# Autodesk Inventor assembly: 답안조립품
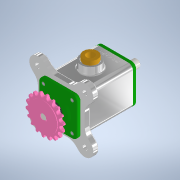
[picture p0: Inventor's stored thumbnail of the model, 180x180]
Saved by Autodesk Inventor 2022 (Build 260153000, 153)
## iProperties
Created: 2022-05
Part Number: 답안조립품
Document SubType Name: Assembly
Designer: Admin
Author: Admin
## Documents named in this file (10)
- C:\Users\Admin\Desktop\720509V1011\답안조립품.iam
- C:\Users\Admin\Desktop\720509V1011\본체.ipt
- C:\Users\Admin\Desktop\720509V1011\조립 부품\커버.ipt
- C:\Users\Admin\Desktop\720509V1011\조립 부품\베어링 6203.ipt
- C:\Users\Admin\Desktop\720509V1011\조립 부품\편심축.ipt
- C:\Users\Admin\Desktop\720509V1011\조립 부품\부시.ipt
- C:\Users\Admin\Desktop\720509V1011\조립 부품\오일 실.ipt
- C:\Users\Admin\Desktop\720509V1011\조립 부품\키 4 x 4 x 14.ipt
- C:\Users\Admin\Desktop\720509V1011\조립 부품\스프로킷.ipt
- C:\Users\Admin\Desktop\720509V1011\조립 부품\볼트 M4.ipt
